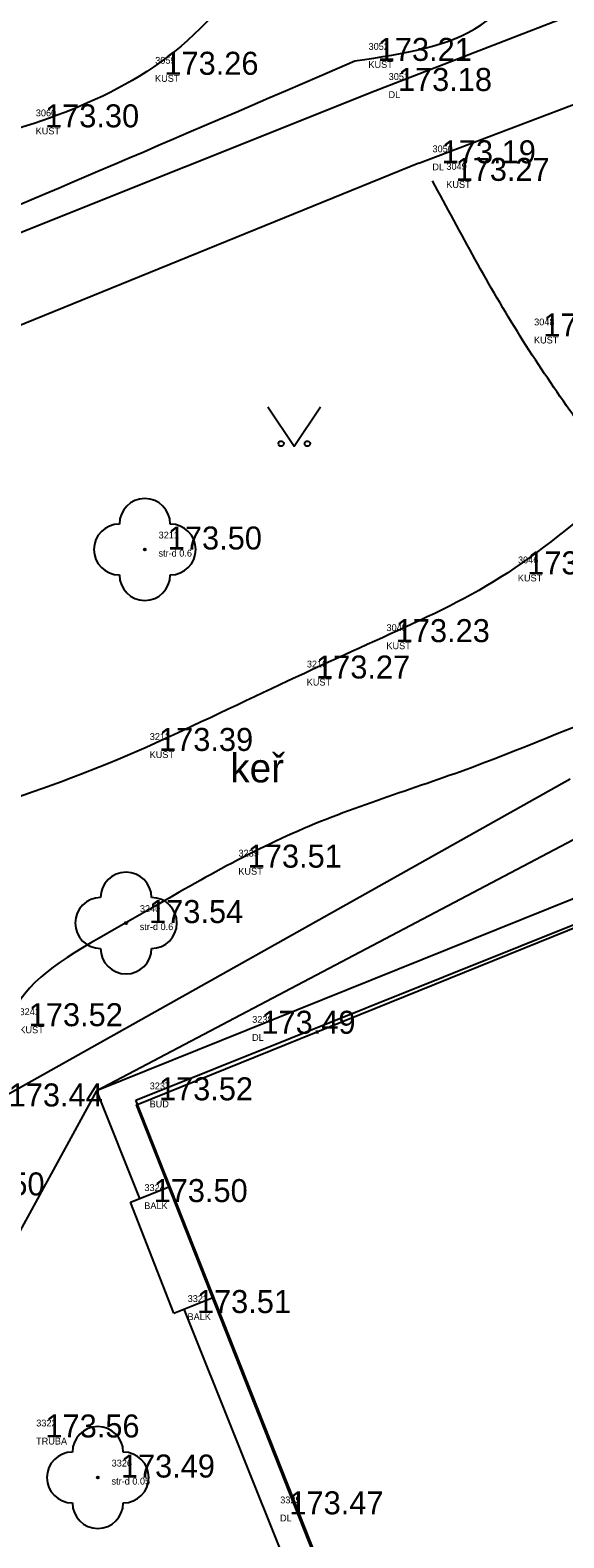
# Model space of a CAD drawing. Extents: x -566117 to -565580, y -1202428 to -1201938.
# Drawn here: x -565670.19 to -565660.05, y -1202067.88 to -1202039.2 of the extents above; entities that cross this region are included whole.
import ezdxf

# ---------------------------------------------------------------- set-up
doc = ezdxf.new("R2010")
doc.units = 0
for name, color, linetype in [('Bod', 7, 'Continuous'), ('BUDOVY_MĚŘ (Construction)', 7, 'Continuous'), ('Implicitní', 7, 'Continuous'), ('Katastr', 7, 'Continuous'), ('Kod', 7, 'Continuous'), ('Výška', 7, 'Continuous'), ('ZELEŇ', 7, 'Continuous'), ('ZN_KULTUR', 7, 'Continuous'), ('Zpevněné plohy', 7, 'Continuous'), ('Číslo', 7, 'Continuous')]:
    doc.layers.add(name, color=color, linetype=linetype)

# ---------------------------------------------------------------- blocks, each defined once
blk = doc.blocks.new('A$C69D74C1E')
at = {"layer": 'Katastr'}
blk.add_lwpolyline([(414.66, -11.52), (417.12, -17.73), (408.59, -21.18), (402.67, -6.19), (396.76, 8.8), (405.25, 12.24), (407.72, 6), (407.94, 6.09), (409.02, 3.38), (408.8, 3.29), (411.19, -2.76), (413.57, -8.78), (413.81, -8.69), (414.89, -11.43), (414.66, -11.52)], dxfattribs=at)
blk = doc.blocks.new('POINT_DISPLAY')
at = {"layer": 'Implicitní'}
blk.add_line((0, 0), (0, 0), dxfattribs=at)
blk = doc.blocks.new('3$13')
at = {"layer": 'ZELEŇ'}
blk.add_circle((0, 0), 0.02, dxfattribs=at)
for centre, start, end in [((0.000055, 0.484), 0, 179.9999972), ((-0.483945, 0), 90, 269.9999972), ((0.484055, 0), 270, 89.9999972), ((0.000055, -0.484), 180.0000028, 0)]:
    blk.add_arc(centre, 0.484, start, end, dxfattribs=at)
blk.add_blockref('POINT_DISPLAY', (0, 0), dxfattribs=at)
blk = doc.blocks.new('3.140_2')
at = {"layer": 'ZN_KULTUR'}
blk.add_lwpolyline([(-1, 1.5), (0, 0), (1, 1.5)], dxfattribs=at)
for centre in [(-0.5, 0.1), (0.5, 0.1)]:
    blk.add_circle(centre, 0.1, dxfattribs=at)

msp = doc.modelspace()

# ---------------------------------------------------------------- linework, layer by layer
at = {"layer": 'BUDOVY_MĚŘ (Construction)'}
for p, q in [((-565656.25, -1202089.756), (-565668.182, -1202059.554)), ((-565668.283, -1202061.49), (-565667.535, -1202061.194)), ((-565667.46, -1202063.601), (-565668.283, -1202061.49)), ((-565667.46, -1202063.601), (-565666.702, -1202063.301))]:
    msp.add_line(p, q, dxfattribs=at)
at = {"layer": 'ZELEŇ'}
for points in [[(-565664.021, -1202039.781), (-565663.033, -1202039.632), (-565661.475, -1202039.398), (-565659.999, -1202037.235), (-565661.553, -1202035.997), (-565662.941, -1202035.416), (-565665.167, -1202035.677), (-565665.941, -1202038.261), (-565667.913, -1202040.139), (-565670.275, -1202041.079), (-565671.815, -1202041.457), (-565672.553, -1202041.639)], [(-565683.152, -1202047.935), (-565682.245, -1202047.506), (-565679.548, -1202046.229), (-565673.092, -1202043.691), (-565667.647, -1202041.344), (-565664.021, -1202039.781)], [(-565658.939, -1202047.807), (-565659.606, -1202046.893), (-565660.94, -1202045.062), (-565662.007, -1202043.063), (-565662.541, -1202042.063)], [(-565658.939, -1202047.807), (-565659.662, -1202048.424), (-565661.102, -1202049.652), (-565663.332, -1202050.683), (-565665.689, -1202051.746), (-565668.512, -1202053.132), (-565671.402, -1202054.146), (-565674.164, -1202054.857), (-565675.522, -1202054.779), (-565676.401, -1202054.728)], [(-565654.454, -1202048.744), (-565655.05, -1202049.716), (-565656.073, -1202051.384), (-565658.538, -1202051.845), (-565661.765, -1202053.301), (-565665.227, -1202054.312), (-565668.549, -1202056.315), (-565670.836, -1202057.51), (-565670.854, -1202060.207), (-565673.917, -1202062.031), (-565676.443, -1202061.669), (-565678.042, -1202061.441)]]:
    msp.add_open_spline(points, degree=3, dxfattribs=at)
at = {"layer": 'Zpevněné plohy'}
for p, q in [((-565663.639, -1202040.353), (-565658.569, -1202038.386)), ((-565662.806, -1202041.729), (-565657.97, -1202039.895)), ((-565674.967, -1202044.874), (-565663.639, -1202040.353)), ((-565662.806, -1202041.729), (-565674.605, -1202046.526)), ((-565671.039, -1202059.671), (-565659.925, -1202053.438)), ((-565659.304, -1202054.306), (-565668.929, -1202059.375)), ((-565659.059, -1202055.397), (-565668.93, -1202059.376)), ((-565668.182, -1202059.554), (-565659.352, -1202056.007)), ((-565668.93, -1202059.376), (-565673.163, -1202067.1)), ((-565668.11, -1202061.421), (-565668.929, -1202059.375)), ((-565664.09, -1202071.452), (-565667.267, -1202063.525))]:
    msp.add_line(p, q, dxfattribs=at)

# ---------------------------------------------------------------- block references
at = {"layer": 'Bod'}
for p in [(-565664.021, -1202039.781), (-565668.078, -1202040.045), (-565663.639, -1202040.353), (-565662.806, -1202041.729), (-565662.541, -1202042.063), (-565660.872, -1202045.022), (-565668.014, -1202049.076), (-565661.18, -1202049.549), (-565663.679, -1202050.838), (-565665.194, -1202051.53), (-565660.207, -1202052.582), (-565668.181, -1202052.908), (-565666.494, -1202055.128), (-565668.37, -1202056.182), (-565666.233, -1202058.288), (-565668.182, -1202059.554), (-565668.283, -1202061.49), (-565667.46, -1202063.601), (-565668.907, -1202066.73), (-565665.702, -1202067.43)]:
    msp.add_blockref('POINT_DISPLAY', p, dxfattribs=at)
at = {"layer": 'Implicitní'}
msp.add_blockref('A$C69D74C1E', (-566064.93, -1202068.44), dxfattribs=at)
at = {"layer": 'ZELEŇ'}
for p in [(-565668.014, -1202049.076), (-565668.37, -1202056.182), (-565668.907, -1202066.73)]:
    msp.add_blockref('3$13', p, dxfattribs=at)
at = {"layer": 'ZN_KULTUR', "xscale": 0.5, "yscale": 0.5}
msp.add_blockref('3.140_2', (-565665.172, -1202047.112), dxfattribs=at)

# ---------------------------------------------------------------- texts
at = {"layer": 'Kod'}
for s, p in [('KUST', (-565663.762, -1202039.915)), ('KUST', (-565667.819, -1202040.179)), ('DL', (-565663.379, -1202040.488)), ('KUST', (-565670.089, -1202041.179)), ('DL', (-565662.546, -1202041.863)), ('KUST', (-565662.282, -1202042.197)), ('KUST', (-565660.613, -1202045.156)), ('str-d 0.6', (-565667.754, -1202049.21)), ('KUST', (-565660.92, -1202049.683)), ('KUST', (-565663.42, -1202050.972)), ('KUST', (-565664.935, -1202051.664)), ('KUST', (-565667.921, -1202053.043)), ('KUST', (-565666.235, -1202055.262)), ('str-d 0.6', (-565668.11, -1202056.316)), ('KUST', (-565670.399, -1202058.278)), ('DL', (-565665.974, -1202058.423)), ('BUD', (-565667.923, -1202059.689)), ('BALK', (-565668.024, -1202061.624)), ('BALK', (-565667.201, -1202063.735)), ('TRUBA', (-565670.081, -1202066.102)), ('str-d 0.05', (-565668.647, -1202066.864)), ('DL', (-565665.442, -1202067.565))]:
    msp.add_text(s, height=0.13, dxfattribs=at).set_placement(p)
at = {"layer": 'Výška'}
for s, p in [('173.21', (-565663.584, -1202039.781)), ('173.26', (-565667.641, -1202040.045)), ('173.18', (-565663.201, -1202040.353)), ('173.30', (-565669.911, -1202041.045)), ('173.19', (-565662.368, -1202041.729)), ('173.27', (-565662.104, -1202042.063)), ('173.27', (-565660.435, -1202045.022)), ('173.50', (-565667.576, -1202049.076)), ('173.26', (-565660.742, -1202049.549)), ('173.23', (-565663.242, -1202050.838)), ('173.27', (-565664.757, -1202051.53)), ('173.39', (-565667.743, -1202052.908)), ('173.51', (-565666.057, -1202055.128)), ('173.54', (-565667.932, -1202056.182)), ('173.52', (-565670.221, -1202058.144)), ('173.49', (-565665.796, -1202058.288)), ('173.44', (-565670.602, -1202059.671)), ('173.52', (-565667.745, -1202059.554)), ('173.50', (-565671.709, -1202061.363)), ('173.50', (-565667.846, -1202061.49)), ('173.51', (-565667.023, -1202063.601)), ('173.56', (-565669.903, -1202065.968)), ('173.49', (-565668.469, -1202066.73)), ('173.47', (-565665.264, -1202067.43))]:
    msp.add_text(s, height=0.4375, dxfattribs=at).set_placement(p)
at = {"layer": 'ZELEŇ'}
msp.add_text('keř', height=0.55, dxfattribs=at).set_placement((-565666.387, -1202053.506))
at = {"layer": 'Číslo'}
for s, p in [('3052', (-565663.759, -1202039.571)), ('3059', (-565667.816, -1202039.835)), ('3051', (-565663.376, -1202040.144)), ('3060', (-565670.086, -1202040.835)), ('3050', (-565662.543, -1202041.519)), ('3049', (-565662.279, -1202041.853)), ('3048', (-565660.61, -1202044.812)), ('3211', (-565667.751, -1202048.866)), ('3046', (-565660.917, -1202049.339)), ('3045', (-565663.417, -1202050.628)), ('3210', (-565664.932, -1202051.32)), ('3212', (-565667.919, -1202052.699)), ('3239', (-565666.232, -1202054.918)), ('3240', (-565668.107, -1202055.972)), ('3241', (-565670.396, -1202057.934)), ('3238', (-565665.971, -1202058.079)), ('3237', (-565667.92, -1202059.345)), ('3324', (-565668.021, -1202061.28)), ('3323', (-565667.198, -1202063.391)), ('3322', (-565670.078, -1202065.758)), ('3326', (-565668.644, -1202066.52)), ('3325', (-565665.439, -1202067.221))]:
    msp.add_text(s, height=0.13, dxfattribs=at).set_placement(p)

doc.saveas('drawing.dxf')
